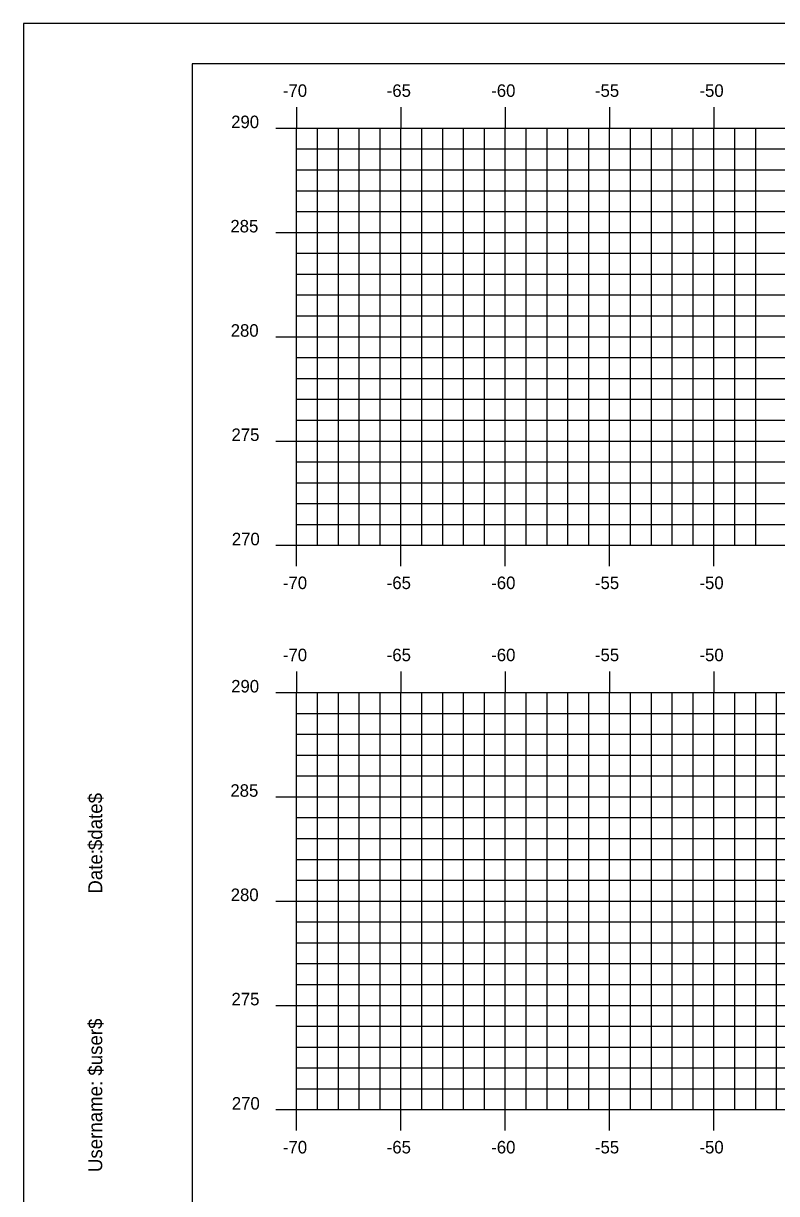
# Model space of a CAD drawing. Extents: x 853340 to 853510, y 366268 to 366378.
# Drawn here: x 853340 to 853376.1, y 366322.1 to 366378.2 of the extents above; entities that cross this region are included whole.
import ezdxf

# ---------------------------------------------------------------- set-up
doc = ezdxf.new("R2010")
doc.units = 0
for name, color, linetype in [('BORDER', 7, 'Continuous'), ('H_V ANNOTATION', 7, 'Continuous'), ('MAJOR', 7, 'Continuous'), ('MINOR', 7, 'Continuous'), ('PLOT BOUNDARY', 7, 'Continuous')]:
    doc.layers.add(name, color=color, linetype=linetype)

msp = doc.modelspace()

# ---------------------------------------------------------------- linework, layer by layer
at = {"layer": 'BORDER'}
for p, q in [((853508.1, 366376.236), (853348.1, 366376.236)), ((853348.1, 366376.236), (853348.1, 366271.236))]:
    msp.add_line(p, q, dxfattribs=at)
at = {"layer": 'MAJOR'}
for p, q in [((853353.1, 366374.158), (853353.1, 366373.156)), ((853358.1, 366374.158), (853358.1, 366373.156)), ((853363.1, 366374.158), (853363.1, 366373.156)), ((853368.1, 366374.158), (853368.1, 366373.156)), ((853373.1, 366374.158), (853373.1, 366373.156)), ((853352.098, 366373.156), (853353.1, 366373.156)), ((853353.1, 366373.156), (853493.1, 366373.156)), ((853353.1, 366353.156), (853353.1, 366373.156)), ((853353.1, 366353.156), (853353.1, 366373.156)), ((853353.1, 366373.156), (853493.1, 366373.156)), ((853358.1, 366353.156), (853358.1, 366373.156)), ((853363.1, 366353.156), (853363.1, 366373.156)), ((853368.1, 366353.156), (853368.1, 366373.156)), ((853373.1, 366353.156), (853373.1, 366373.156)), ((853352.098, 366368.156), (853353.1, 366368.156)), ((853353.1, 366368.156), (853493.1, 366368.156)), ((853352.098, 366363.156), (853353.1, 366363.156)), ((853353.1, 366363.156), (853493.1, 366363.156)), ((853352.098, 366358.156), (853353.1, 366358.156)), ((853353.1, 366358.156), (853493.1, 366358.156)), ((853352.098, 366353.156), (853353.1, 366353.156)), ((853353.1, 366353.156), (853493.1, 366353.156)), ((853353.1, 366353.156), (853493.1, 366353.156)), ((853353.1, 366352.154), (853353.1, 366353.156)), ((853358.1, 366352.154), (853358.1, 366353.156)), ((853363.1, 366352.154), (853363.1, 366353.156)), ((853368.1, 366352.154), (853368.1, 366353.156)), ((853373.1, 366352.154), (853373.1, 366353.156)), ((853353.1, 366347.101), (853353.1, 366346.099)), ((853358.1, 366347.101), (853358.1, 366346.099)), ((853363.1, 366347.101), (853363.1, 366346.099)), ((853368.1, 366347.101), (853368.1, 366346.099)), ((853373.1, 366347.101), (853373.1, 366346.099)), ((853352.098, 366346.099), (853353.1, 366346.099)), ((853353.1, 366346.099), (853493.1, 366346.099)), ((853353.1, 366326.099), (853353.1, 366346.099)), ((853353.1, 366326.099), (853353.1, 366346.099)), ((853353.1, 366346.099), (853493.1, 366346.099)), ((853358.1, 366326.099), (853358.1, 366346.099)), ((853363.1, 366326.099), (853363.1, 366346.099)), ((853368.1, 366326.099), (853368.1, 366346.099)), ((853373.1, 366326.099), (853373.1, 366346.099)), ((853352.098, 366341.099), (853353.1, 366341.099)), ((853353.1, 366341.099), (853493.1, 366341.099)), ((853352.098, 366336.099), (853353.1, 366336.099)), ((853353.1, 366336.099), (853493.1, 366336.099)), ((853352.098, 366331.099), (853353.1, 366331.099)), ((853353.1, 366331.099), (853493.1, 366331.099)), ((853352.098, 366326.099), (853353.1, 366326.099)), ((853353.1, 366326.099), (853493.1, 366326.099)), ((853353.1, 366326.099), (853493.1, 366326.099)), ((853353.1, 366325.097), (853353.1, 366326.099)), ((853358.1, 366325.097), (853358.1, 366326.099)), ((853363.1, 366325.097), (853363.1, 366326.099)), ((853368.1, 366325.097), (853368.1, 366326.099)), ((853373.1, 366325.097), (853373.1, 366326.099))]:
    msp.add_line(p, q, dxfattribs=at)
at = {"layer": 'MINOR'}
for p, q in [((853354.1, 366353.156), (853354.1, 366373.156)), ((853355.1, 366353.156), (853355.1, 366373.156)), ((853356.1, 366353.156), (853356.1, 366373.156)), ((853357.1, 366353.156), (853357.1, 366373.156)), ((853359.1, 366353.156), (853359.1, 366373.156)), ((853360.1, 366353.156), (853360.1, 366373.156)), ((853361.1, 366353.156), (853361.1, 366373.156)), ((853362.1, 366353.156), (853362.1, 366373.156)), ((853364.1, 366353.156), (853364.1, 366373.156)), ((853365.1, 366353.156), (853365.1, 366373.156)), ((853366.1, 366353.156), (853366.1, 366373.156)), ((853367.1, 366353.156), (853367.1, 366373.156)), ((853369.1, 366353.156), (853369.1, 366373.156)), ((853370.1, 366353.156), (853370.1, 366373.156)), ((853371.1, 366353.156), (853371.1, 366373.156)), ((853372.1, 366353.156), (853372.1, 366373.156)), ((853374.1, 366353.156), (853374.1, 366373.156)), ((853375.1, 366353.156), (853375.1, 366373.156)), ((853353.1, 366372.156), (853493.1, 366372.156)), ((853353.1, 366372.156), (853354.102, 366372.156)), ((853353.1, 366371.156), (853493.1, 366371.156)), ((853353.1, 366371.156), (853354.102, 366371.156)), ((853353.1, 366370.156), (853493.1, 366370.156)), ((853353.1, 366370.156), (853354.102, 366370.156)), ((853353.1, 366369.156), (853493.1, 366369.156)), ((853353.1, 366369.156), (853354.102, 366369.156)), ((853353.1, 366367.156), (853493.1, 366367.156)), ((853353.1, 366367.156), (853354.102, 366367.156)), ((853353.1, 366366.156), (853493.1, 366366.156)), ((853353.1, 366366.156), (853354.102, 366366.156)), ((853353.1, 366365.156), (853493.1, 366365.156)), ((853353.1, 366365.156), (853354.102, 366365.156)), ((853353.1, 366364.156), (853493.1, 366364.156)), ((853353.1, 366364.156), (853354.102, 366364.156)), ((853353.1, 366362.156), (853493.1, 366362.156)), ((853353.1, 366362.156), (853354.102, 366362.156)), ((853353.1, 366361.156), (853493.1, 366361.156)), ((853353.1, 366361.156), (853354.102, 366361.156)), ((853353.1, 366360.156), (853493.1, 366360.156)), ((853353.1, 366360.156), (853354.102, 366360.156)), ((853353.1, 366359.156), (853493.1, 366359.156)), ((853353.1, 366359.156), (853354.102, 366359.156)), ((853353.1, 366357.156), (853493.1, 366357.156)), ((853353.1, 366357.156), (853354.102, 366357.156)), ((853353.1, 366356.156), (853493.1, 366356.156)), ((853353.1, 366356.156), (853354.102, 366356.156)), ((853353.1, 366355.156), (853493.1, 366355.156)), ((853353.1, 366355.156), (853354.102, 366355.156)), ((853353.1, 366354.156), (853493.1, 366354.156)), ((853353.1, 366354.156), (853354.102, 366354.156)), ((853353.1, 366326.099), (853353.1, 366346.099)), ((853354.1, 366326.099), (853354.1, 366346.099)), ((853355.1, 366326.099), (853355.1, 366346.099)), ((853356.1, 366326.099), (853356.1, 366346.099)), ((853357.1, 366326.099), (853357.1, 366346.099)), ((853359.1, 366326.099), (853359.1, 366346.099)), ((853360.1, 366326.099), (853360.1, 366346.099)), ((853361.1, 366326.099), (853361.1, 366346.099)), ((853362.1, 366326.099), (853362.1, 366346.099)), ((853364.1, 366326.099), (853364.1, 366346.099)), ((853365.1, 366326.099), (853365.1, 366346.099)), ((853366.1, 366326.099), (853366.1, 366346.099)), ((853367.1, 366326.099), (853367.1, 366346.099)), ((853369.1, 366326.099), (853369.1, 366346.099)), ((853370.1, 366326.099), (853370.1, 366346.099)), ((853371.1, 366326.099), (853371.1, 366346.099)), ((853372.1, 366326.099), (853372.1, 366346.099)), ((853374.1, 366326.099), (853374.1, 366346.099)), ((853375.1, 366326.099), (853375.1, 366346.099)), ((853376.1, 366326.099), (853376.1, 366346.099)), ((853353.1, 366345.099), (853493.1, 366345.099)), ((853353.1, 366345.099), (853354.102, 366345.099)), ((853353.1, 366344.099), (853493.1, 366344.099)), ((853353.1, 366344.099), (853354.102, 366344.099)), ((853353.1, 366343.099), (853493.1, 366343.099)), ((853353.1, 366343.099), (853354.102, 366343.099)), ((853353.1, 366342.099), (853493.1, 366342.099)), ((853353.1, 366342.099), (853354.102, 366342.099)), ((853353.1, 366340.099), (853493.1, 366340.099)), ((853353.1, 366340.099), (853354.102, 366340.099)), ((853353.1, 366339.099), (853493.1, 366339.099)), ((853353.1, 366339.099), (853354.102, 366339.099)), ((853353.1, 366338.099), (853493.1, 366338.099)), ((853353.1, 366338.099), (853354.102, 366338.099)), ((853353.1, 366337.099), (853493.1, 366337.099)), ((853353.1, 366337.099), (853354.102, 366337.099)), ((853353.1, 366335.099), (853493.1, 366335.099)), ((853353.1, 366335.099), (853354.102, 366335.099)), ((853353.1, 366334.099), (853493.1, 366334.099)), ((853353.1, 366334.099), (853354.102, 366334.099)), ((853353.1, 366333.099), (853493.1, 366333.099)), ((853353.1, 366333.099), (853354.102, 366333.099)), ((853353.1, 366332.099), (853493.1, 366332.099)), ((853353.1, 366332.099), (853354.102, 366332.099)), ((853353.1, 366330.099), (853493.1, 366330.099)), ((853353.1, 366330.099), (853354.102, 366330.099)), ((853353.1, 366329.099), (853493.1, 366329.099)), ((853353.1, 366329.099), (853354.102, 366329.099)), ((853353.1, 366328.099), (853493.1, 366328.099)), ((853353.1, 366328.099), (853354.102, 366328.099)), ((853353.1, 366327.099), (853493.1, 366327.099)), ((853353.1, 366327.099), (853354.102, 366327.099))]:
    msp.add_line(p, q, dxfattribs=at)
at = {"layer": 'PLOT BOUNDARY'}
msp.add_lwpolyline([(853340.007, 366268.177), (853510.007, 366268.177), (853510.007, 366378.177), (853340.007, 366378.177)], close=True, dxfattribs=at)

# ---------------------------------------------------------------- texts
at = {"layer": 'BORDER'}
for s, p in [('$date$', (853343.785, 366338.542)), ('Date:', (853343.785, 366336.453)), ('$user$', (853343.785, 366327.728)), ('Username:', (853343.785, 366323.104))]:
    msp.add_text(s, height=0.6696, rotation=90, dxfattribs=at).set_placement(p)
at = {"layer": 'H_V ANNOTATION'}
for s, p in [('-70', (853352.441, 366374.656)), ('-65', (853357.417, 366374.656)), ('-60', (853362.425, 366374.656)), ('-55', (853367.396, 366374.656)), ('-50', (853372.404, 366374.656)), ('290', (853349.962, 366373.156)), ('285', (853349.924, 366368.156)), ('280', (853349.94, 366363.156)), ('275', (853349.978, 366358.156)), ('270', (853349.994, 366353.156)), ('-70', (853352.441, 366351.056)), ('-65', (853357.417, 366351.056)), ('-60', (853362.425, 366351.056)), ('-55', (853367.396, 366351.056)), ('-50', (853372.404, 366351.056)), ('-70', (853352.441, 366347.599)), ('-65', (853357.417, 366347.599)), ('-60', (853362.425, 366347.599)), ('-55', (853367.396, 366347.599)), ('-50', (853372.404, 366347.599)), ('290', (853349.962, 366346.099)), ('285', (853349.924, 366341.099)), ('280', (853349.94, 366336.099)), ('275', (853349.978, 366331.099)), ('270', (853349.994, 366326.099)), ('-70', (853352.441, 366323.999)), ('-65', (853357.417, 366323.999)), ('-60', (853362.425, 366323.999)), ('-55', (853367.396, 366323.999)), ('-50', (853372.404, 366323.999))]:
    msp.add_text(s, height=0.6, dxfattribs=at).set_placement(p)
at = {"layer": 'MAJOR'}
for p in [(853353.095, 366353.156), (853353.095, 366326.099)]:
    msp.add_text('-', height=0.00000006, rotation=53.1301, dxfattribs=at).set_placement(p)

doc.saveas('drawing.dxf')
